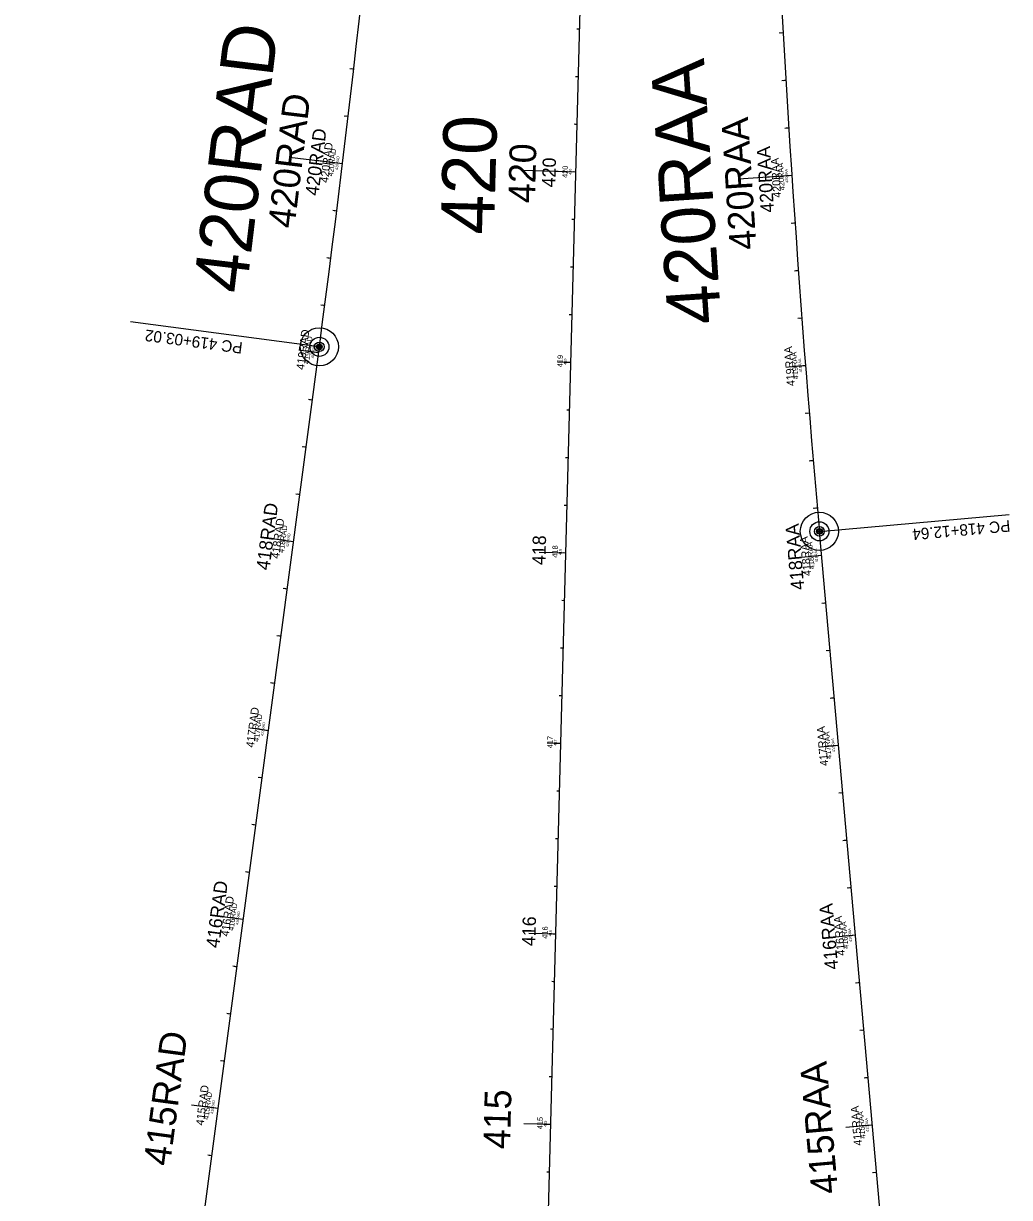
# Model space of a CAD drawing. Extents: x 564646 to 607088, y 225853 to 261760.
# Drawn here: x 598692 to 599209, y 255654 to 256270 of the extents above; entities that cross this region are included whole.
import ezdxf

# ---------------------------------------------------------------- set-up
doc = ezdxf.new("R2010")
doc.units = 0
for name, color, linetype in [('B_CONC_HIDDEN_LT', 7, 'Continuous'), ('B_CONST', 7, 'Continuous'), ('B_EXIST', 7, 'Continuous'), ('B_TEXT', 7, 'Continuous'), ('E-Easements', 7, 'Continuous'), ('E-Property Lines', 7, 'Continuous'), ('E_ALI_100', 7, 'Continuous'), ('E_RW_CorporateLimits', 7, 'Continuous'), ('E_RW_EasementUtility_Text', 7, 'Continuous'), ('E_WTR_FlowLine', 7, 'Continuous'), ('EMCS_SURVEY_PT CODES', 7, 'Continuous'), ('EMCS_SURVEY_PT ELEV', 7, 'Continuous'), ('EMCS_SURVEY_PT NOTES', 7, 'Continuous'), ('Level 33', 7, 'Continuous'), ('P-Easements Floodplain', 7, 'Continuous'), ('P-Easements Temporary', 7, 'Continuous'), ('P_ALI_100_Tic', 7, 'Continuous'), ('P_ALI_20', 7, 'Continuous'), ('P_RW_AccessPreviousProject Txt', 7, 'Continuous'), ('P_RW_EasementPerm', 7, 'Continuous'), ('P_RW_EasementTemp', 7, 'Continuous'), ('P_RW_PropertyConnector', 7, 'Continuous'), ('P_RW_Proposed', 7, 'Continuous'), ('P_WAL', 7, 'Continuous')]:
    doc.layers.add(name, color=color, linetype=linetype)

msp = doc.modelspace()

# ---------------------------------------------------------------- linework, layer by layer
at = {"layer": 'B_CONC_HIDDEN_LT'}
for p, q in [((598400.93, 234167.82), (599016.61, 257518.82)), ((598699.97, 254993.78), (598847.11, 256100.02)), ((599199.94, 254988.24), (599109.45, 256003.2))]:
    msp.add_line(p, q, dxfattribs=at)
for centre, start, end in [((590916.95, 257154.8), 352.423638, 358.489658), ((607077.84, 256713.66), 179.635421, 185.095011)]:
    msp.add_arc(centre, 8000, start, end, dxfattribs=at)
at = {"layer": 'B_CONST'}
for centre in [(598847.11, 256100.02), (599109.45, 256003.2)]:
    msp.add_circle(centre, 1.5, dxfattribs=at)
at = {"layer": 'B_EXIST'}
for centre in [(598847.11, 256100.02), (599109.45, 256003.2)]:
    msp.add_circle(centre, 5, dxfattribs=at)
at = {"layer": 'B_TEXT'}
for points in [[(598847.11, 256100.02), (598747.99, 256113.21)], [(599109.45, 256003.2), (599209.05, 256012.08)]]:
    msp.add_lwpolyline(points, dxfattribs=at)
at = {"layer": 'E-Easements'}
for centre in [(598847.11, 256100.02), (599109.45, 256003.2)]:
    msp.add_circle(centre, 2.5, dxfattribs=at)
at = {"layer": 'E_ALI_100'}
for points in [[(598982.2, 256266.91), (598983.6, 256266.88)], [(599089.04, 256264.78), (599090.44, 256264.86)], [(598863.76, 256246.04), (598865.15, 256245.88)], [(598981.54, 256241.92), (598982.94, 256241.88)], [(599090.48, 256239.82), (599091.88, 256239.9)], [(598860.88, 256221.21), (598862.27, 256221.05)], [(598980.88, 256216.93), (598982.28, 256216.89)], [(599092, 256214.86), (599093.4, 256214.94)], [(598856.54, 256196.56), (598859.32, 256196.23)], [(598978.83, 256191.98), (598981.62, 256191.9)], [(599092.2, 256189.81), (599095, 256190)], [(598854.89, 256171.58), (598856.28, 256171.41)], [(598979.57, 256166.95), (598980.97, 256166.91)], [(599095.28, 256164.96), (599096.67, 256165.05)], [(598851.78, 256146.78), (598853.17, 256146.6)], [(598978.91, 256141.96), (598980.31, 256141.92)], [(599097.03, 256140.01), (599098.43, 256140.11)], [(598848.59, 256121.99), (598849.98, 256121.81)], [(598978.25, 256116.96), (598979.65, 256116.93)], [(599098.86, 256115.08), (599100.26, 256115.18)], [(598843.94, 256097.39), (598846.71, 256097.02)], [(598976.19, 256092.01), (598978.99, 256091.94)], [(599099.38, 256090.04), (599102.17, 256090.25)], [(598842.03, 256072.43), (598843.42, 256072.24)], [(598976.93, 256066.98), (598978.33, 256066.95)], [(599102.76, 256065.22), (599104.15, 256065.33)], [(598838.73, 256047.64), (598840.12, 256047.46)], [(598976.27, 256041.99), (598977.67, 256041.95)], [(599104.82, 256040.3), (599106.22, 256040.42)], [(598835.44, 256022.86), (598836.83, 256022.68)], [(598975.61, 256017), (598977.01, 256016.96)], [(599106.97, 256015.39), (599108.36, 256015.51)], [(598830.75, 255998.27), (598833.53, 255997.9)], [(598973.55, 255992.05), (598976.35, 255991.97)], [(599107.78, 255990.36), (599110.57, 255990.61)], [(598828.85, 255973.3), (598830.23, 255973.11)], [(598974.3, 255967.02), (598975.69, 255966.98)], [(599111.4, 255965.58), (599112.79, 255965.71)], [(598825.55, 255948.52), (598826.94, 255948.33)], [(598973.64, 255942.03), (598975.04, 255941.99)], [(599113.62, 255940.68), (599115.01, 255940.81)], [(598822.25, 255923.74), (598823.64, 255923.55)], [(598972.98, 255917.03), (598974.38, 255917)], [(599115.84, 255915.78), (599117.23, 255915.9)], [(598817.57, 255899.14), (598820.34, 255898.77)], [(598970.92, 255892.08), (598973.72, 255892.01)], [(599116.66, 255890.75), (599119.45, 255891)], [(598815.66, 255874.17), (598817.05, 255873.99)], [(598971.66, 255867.05), (598973.06, 255867.01)], [(599120.28, 255865.98), (599121.67, 255866.1)], [(598812.36, 255849.39), (598813.75, 255849.21)], [(598971, 255842.06), (598972.4, 255842.02)], [(599122.5, 255841.08), (599123.89, 255841.2)], [(598809.07, 255824.61), (598810.46, 255824.42)], [(598970.34, 255817.07), (598971.74, 255817.03)], [(599124.72, 255816.18), (599126.11, 255816.3)], [(598804.38, 255800.01), (598807.16, 255799.64)], [(598968.28, 255792.11), (598971.08, 255792.04)], [(599125.54, 255791.15), (599128.33, 255791.4)], [(598802.48, 255775.04), (598803.86, 255774.86)], [(598969.02, 255767.09), (598970.42, 255767.05)], [(599129.16, 255766.37), (599130.55, 255766.5)], [(598799.18, 255750.26), (598800.57, 255750.08)], [(598968.36, 255742.1), (598969.76, 255742.06)], [(599131.38, 255741.47), (599132.77, 255741.6)], [(598795.88, 255725.48), (598797.27, 255725.3)], [(598967.71, 255717.1), (598969.11, 255717.07)], [(599133.6, 255716.57), (599134.99, 255716.69)], [(598791.2, 255700.88), (598793.98, 255700.51)], [(598965.65, 255692.15), (598968.45, 255692.08)], [(599134.43, 255691.54), (599137.21, 255691.79)], [(598789.29, 255675.92), (598790.68, 255675.73)], [(598966.39, 255667.12), (598967.79, 255667.08)], [(599138.04, 255666.77), (599139.43, 255666.89)]]:
    msp.add_lwpolyline(points, dxfattribs=at)
at = {"layer": 'E_WTR_FlowLine'}
for centre in [(598847.11, 256100.02), (599109.45, 256003.2)]:
    msp.add_circle(centre, 0.5, dxfattribs=at)
at = {"layer": 'EMCS_SURVEY_PT CODES'}
for p, q in [((598400.93, 234167.82), (599016.61, 257518.82)), ((598699.97, 254993.78), (598847.11, 256100.02)), ((599199.94, 254988.24), (599109.45, 256003.2))]:
    msp.add_line(p, q, dxfattribs=at)
for centre, start, end in [((590916.95, 257154.8), 352.423638, 358.489658), ((607077.84, 256713.66), 179.635421, 185.095011)]:
    msp.add_arc(centre, 8000, start, end, dxfattribs=at)
at = {"layer": 'EMCS_SURVEY_PT ELEV'}
for p, q in [((598400.93, 234167.82), (599016.61, 257518.82)), ((598400.93, 234167.82), (599016.61, 257518.82)), ((598699.97, 254993.78), (598847.11, 256100.02)), ((599199.94, 254988.24), (599109.45, 256003.2))]:
    msp.add_line(p, q, dxfattribs=at)
for centre, start, end in [((590916.95, 257154.8), 352.423638, 358.489658), ((607077.84, 256713.66), 179.635421, 185.095011)]:
    msp.add_arc(centre, 8000, start, end, dxfattribs=at)
at = {"layer": 'Level 33'}
for points in [[(598982.9, 256266.89), (598983.6, 256266.88)], [(599089.74, 256264.82), (599090.44, 256264.86)], [(598864.46, 256245.96), (598865.15, 256245.88)], [(598982.24, 256241.9), (598982.94, 256241.88)], [(599091.18, 256239.86), (599091.88, 256239.9)], [(598861.58, 256221.13), (598862.27, 256221.05)], [(598981.58, 256216.91), (598982.28, 256216.89)], [(599092.7, 256214.9), (599093.4, 256214.94)], [(598857.93, 256196.39), (598859.32, 256196.23)], [(598980.23, 256191.94), (598981.62, 256191.9)], [(599093.6, 256189.9), (599095, 256190)], [(598855.59, 256171.5), (598856.28, 256171.41)], [(598980.27, 256166.93), (598980.97, 256166.91)], [(599095.97, 256165), (599096.67, 256165.05)], [(598852.48, 256146.69), (598853.17, 256146.6)], [(598979.61, 256141.94), (598980.31, 256141.92)], [(599097.73, 256140.06), (599098.43, 256140.11)], [(598849.29, 256121.9), (598849.98, 256121.81)], [(598978.95, 256116.95), (598979.65, 256116.93)], [(599099.56, 256115.13), (599100.26, 256115.18)], [(598845.33, 256097.21), (598846.71, 256097.02)], [(598977.59, 256091.97), (598978.99, 256091.94)], [(599100.77, 256090.14), (599102.17, 256090.25)], [(598842.72, 256072.33), (598843.42, 256072.24)], [(598977.63, 256066.96), (598978.33, 256066.95)], [(599103.46, 256065.28), (599104.15, 256065.33)], [(598839.43, 256047.55), (598840.12, 256047.46)], [(598976.97, 256041.97), (598977.67, 256041.95)], [(599105.52, 256040.36), (599106.22, 256040.42)], [(598836.13, 256022.77), (598836.83, 256022.68)], [(598976.31, 256016.98), (598977.01, 256016.96)], [(599107.66, 256015.45), (599108.36, 256015.51)], [(598832.14, 255998.08), (598833.53, 255997.9)], [(598974.95, 255992.01), (598976.35, 255991.97)], [(599109.18, 255990.48), (599110.57, 255990.61)], [(598829.54, 255973.21), (598830.23, 255973.11)], [(598974.99, 255967), (598975.69, 255966.98)], [(599112.1, 255965.64), (599112.79, 255965.71)], [(598826.24, 255948.42), (598826.94, 255948.33)], [(598974.34, 255942.01), (598975.04, 255941.99)], [(599114.32, 255940.74), (599115.01, 255940.81)], [(598822.95, 255923.64), (598823.64, 255923.55)], [(598973.68, 255917.02), (598974.38, 255917)], [(599116.54, 255915.84), (599117.23, 255915.9)], [(598818.96, 255898.95), (598820.34, 255898.77)], [(598972.32, 255892.04), (598973.72, 255892.01)], [(599118.06, 255890.88), (599119.45, 255891)], [(598816.35, 255874.08), (598817.05, 255873.99)], [(598972.36, 255867.03), (598973.06, 255867.01)], [(599120.98, 255866.04), (599121.67, 255866.1)], [(598813.06, 255849.3), (598813.75, 255849.21)], [(598971.7, 255842.04), (598972.4, 255842.02)], [(599123.2, 255841.14), (599123.89, 255841.2)], [(598809.76, 255824.52), (598810.46, 255824.42)], [(598971.04, 255817.05), (598971.74, 255817.03)], [(599125.42, 255816.24), (599126.11, 255816.3)], [(598805.77, 255799.83), (598807.16, 255799.64)], [(598969.68, 255792.08), (598971.08, 255792.04)], [(599126.94, 255791.27), (599128.33, 255791.4)], [(598803.17, 255774.95), (598803.86, 255774.86)], [(598969.72, 255767.07), (598970.42, 255767.05)], [(599129.86, 255766.43), (599130.55, 255766.5)], [(598799.87, 255750.17), (598800.57, 255750.08)], [(598969.06, 255742.08), (598969.76, 255742.06)], [(599132.08, 255741.53), (599132.77, 255741.6)], [(598796.58, 255725.39), (598797.27, 255725.3)], [(598968.41, 255717.09), (598969.11, 255717.07)], [(599134.3, 255716.63), (599134.99, 255716.69)], [(598792.59, 255700.7), (598793.98, 255700.51)], [(598967.05, 255692.11), (598968.45, 255692.08)], [(599135.82, 255691.67), (599137.21, 255691.79)], [(598789.99, 255675.83), (598790.68, 255675.73)], [(598967.09, 255667.1), (598967.79, 255667.08)], [(599138.74, 255666.83), (599139.43, 255666.89)]]:
    msp.add_lwpolyline(points, dxfattribs=at)
at = {"layer": 'P-Easements Floodplain'}
for p, q in [((598400.93, 234167.82), (599016.61, 257518.82)), ((598699.97, 254993.78), (598847.11, 256100.02)), ((599199.94, 254988.24), (599109.45, 256003.2))]:
    msp.add_line(p, q, dxfattribs=at)
for centre, start, end in [((590916.95, 257154.8), 352.423638, 358.489658), ((607077.84, 256713.66), 179.635421, 185.095011)]:
    msp.add_arc(centre, 8000, start, end, dxfattribs=at)
at = {"layer": 'P-Easements Temporary'}
for centre in [(598847.11, 256100.02), (599109.45, 256003.2)]:
    msp.add_circle(centre, 10, dxfattribs=at)
at = {"layer": 'P_ALI_100_Tic'}
for points in [[(598831.52, 256199.58), (598859.32, 256196.23)], [(598953.63, 256192.64), (598981.62, 256191.9)], [(599067.06, 256188.16), (599095, 256190)], [(598819.65, 255999.74), (598833.53, 255997.9)], [(598962.36, 255992.34), (598976.35, 255991.97)], [(599096.63, 255989.36), (599110.57, 255990.61)], [(598793.28, 255801.49), (598807.16, 255799.64)], [(598957.09, 255792.41), (598971.08, 255792.04)], [(599114.39, 255790.15), (599128.33, 255791.4)]]:
    msp.add_lwpolyline(points, dxfattribs=at)
at = {"layer": 'P_ALI_20'}
for points in [[(598845.42, 256197.9), (598859.32, 256196.23)], [(598967.63, 256192.27), (598981.62, 256191.9)], [(599081.03, 256189.08), (599095, 256190)], [(598839.78, 256097.95), (598846.71, 256097.02)], [(598971.99, 256092.12), (598978.99, 256091.94)], [(599095.19, 256089.71), (599102.17, 256090.25)], [(598826.59, 255998.82), (598833.53, 255997.9)], [(598969.36, 255992.16), (598976.35, 255991.97)], [(599103.6, 255989.99), (599110.57, 255990.61)], [(598813.41, 255899.69), (598820.34, 255898.77)], [(598966.72, 255892.19), (598973.72, 255892.01)], [(599112.48, 255890.38), (599119.45, 255891)], [(598800.22, 255800.56), (598807.16, 255799.64)], [(598964.08, 255792.23), (598971.08, 255792.04)], [(599121.36, 255790.78), (599128.33, 255791.4)], [(598780.1, 255702.36), (598793.98, 255700.51)], [(598954.45, 255692.44), (598968.45, 255692.08)], [(599123.27, 255690.55), (599137.21, 255691.79)]]:
    msp.add_lwpolyline(points, dxfattribs=at)
at = {"layer": 'P_RW_AccessPreviousProject Txt'}
for points in [[(599088.34, 256264.74), (599090.44, 256264.86)], [(598863.07, 256246.12), (598865.15, 256245.88)], [(598863.07, 256246.12), (598865.15, 256245.88)], [(599089.78, 256239.77), (599091.88, 256239.9)], [(598860.19, 256221.29), (598862.27, 256221.05)], [(598860.19, 256221.29), (598862.27, 256221.05)], [(599091.3, 256214.81), (599093.4, 256214.94)], [(598855.15, 256196.73), (598859.32, 256196.23)], [(598855.15, 256196.73), (598859.32, 256196.23)], [(599090.81, 256189.72), (599095, 256190)], [(598854.2, 256171.67), (598856.28, 256171.41)], [(598854.2, 256171.67), (598856.28, 256171.41)], [(599094.58, 256164.91), (599096.67, 256165.05)], [(598851.09, 256146.87), (598853.17, 256146.6)], [(598851.09, 256146.87), (598853.17, 256146.6)], [(599096.33, 256139.96), (599098.43, 256140.11)], [(598847.9, 256122.08), (598849.98, 256121.81)], [(598847.9, 256122.08), (598849.98, 256121.81)], [(599098.16, 256115.02), (599100.26, 256115.18)], [(598842.55, 256097.58), (598846.71, 256097.02)], [(598842.55, 256097.58), (598846.71, 256097.02)], [(599097.98, 256089.93), (599102.17, 256090.25)], [(598841.34, 256072.52), (598843.42, 256072.24)], [(598841.34, 256072.52), (598843.42, 256072.24)], [(599102.06, 256065.16), (599104.15, 256065.33)], [(598838.04, 256047.74), (598840.12, 256047.46)], [(598838.04, 256047.74), (598840.12, 256047.46)], [(599104.13, 256040.24), (599106.22, 256040.42)], [(598834.74, 256022.95), (598836.83, 256022.68)], [(598834.74, 256022.95), (598836.83, 256022.68)], [(599106.27, 256015.33), (599108.36, 256015.51)], [(598829.37, 255998.45), (598833.53, 255997.9)], [(598829.37, 255998.45), (598833.53, 255997.9)], [(599106.39, 255990.24), (599110.57, 255990.61)], [(598828.15, 255973.39), (598830.23, 255973.11)], [(598828.15, 255973.39), (598830.23, 255973.11)], [(599110.7, 255965.52), (599112.79, 255965.71)], [(598824.86, 255948.61), (598826.94, 255948.33)], [(598824.86, 255948.61), (598826.94, 255948.33)], [(599112.92, 255940.62), (599115.01, 255940.81)], [(598821.56, 255923.83), (598823.64, 255923.55)], [(598821.56, 255923.83), (598823.64, 255923.55)], [(599115.14, 255915.72), (599117.23, 255915.9)], [(598816.18, 255899.32), (598820.34, 255898.77)], [(598816.18, 255899.32), (598820.34, 255898.77)], [(599115.27, 255890.63), (599119.45, 255891)], [(598814.97, 255874.26), (598817.05, 255873.99)], [(598814.97, 255874.26), (598817.05, 255873.99)], [(599119.58, 255865.92), (599121.67, 255866.1)], [(598811.67, 255849.48), (598813.75, 255849.21)], [(598811.67, 255849.48), (598813.75, 255849.21)], [(599121.8, 255841.01), (599123.89, 255841.2)], [(598808.37, 255824.7), (598810.46, 255824.42)], [(598808.37, 255824.7), (598810.46, 255824.42)], [(599124.02, 255816.11), (599126.11, 255816.3)], [(598803, 255800.2), (598807.16, 255799.64)], [(598803, 255800.2), (598807.16, 255799.64)], [(599124.15, 255791.03), (599128.33, 255791.4)], [(598801.78, 255775.14), (598803.86, 255774.86)], [(598801.78, 255775.14), (598803.86, 255774.86)], [(599128.46, 255766.31), (599130.55, 255766.5)], [(598798.49, 255750.36), (598800.57, 255750.08)], [(598798.49, 255750.36), (598800.57, 255750.08)], [(599130.68, 255741.41), (599132.77, 255741.6)], [(598795.19, 255725.57), (598797.27, 255725.3)], [(598795.19, 255725.57), (598797.27, 255725.3)], [(599132.9, 255716.51), (599134.99, 255716.69)], [(598789.81, 255701.07), (598793.98, 255700.51)], [(598789.81, 255701.07), (598793.98, 255700.51)], [(599133.03, 255691.42), (599137.21, 255691.79)], [(598788.6, 255676.01), (598790.68, 255675.73)], [(598788.6, 255676.01), (598790.68, 255675.73)], [(599137.34, 255666.71), (599139.43, 255666.89)]]:
    msp.add_lwpolyline(points, dxfattribs=at)
at = {"layer": 'P_RW_EasementPerm'}
for points in [[(598852.37, 256197.06), (598859.32, 256196.23)], [(598974.63, 256192.09), (598981.62, 256191.9)], [(599088.01, 256189.54), (599095, 256190)], [(598843.24, 256097.48), (598846.71, 256097.02)], [(598975.49, 256092.03), (598978.99, 256091.94)], [(599098.68, 256089.98), (599102.17, 256090.25)], [(598826.59, 255998.82), (598833.53, 255997.9)], [(598969.36, 255992.16), (598976.35, 255991.97)], [(599103.6, 255989.99), (599110.57, 255990.61)], [(598816.88, 255899.23), (598820.34, 255898.77)], [(598970.22, 255892.1), (598973.72, 255892.01)], [(599115.97, 255890.69), (599119.45, 255891)], [(598800.22, 255800.56), (598807.16, 255799.64)], [(598964.08, 255792.23), (598971.08, 255792.04)], [(599121.36, 255790.78), (599128.33, 255791.4)], [(598790.51, 255700.98), (598793.98, 255700.51)], [(598964.95, 255692.17), (598968.45, 255692.08)], [(599133.73, 255691.48), (599137.21, 255691.79)]]:
    msp.add_lwpolyline(points, dxfattribs=at)
at = {"layer": 'P_RW_EasementTemp'}
for p, q in [((598400.93, 234167.82), (599016.61, 257518.82)), ((598699.97, 254993.78), (598847.11, 256100.02)), ((599199.94, 254988.24), (599109.45, 256003.2))]:
    msp.add_line(p, q, dxfattribs=at)
for centre, start, end in [((590916.95, 257154.8), 352.423638, 358.489658), ((607077.84, 256713.66), 179.635421, 185.095011)]:
    msp.add_arc(centre, 8000, start, end, dxfattribs=at)
at = {"layer": 'P_RW_PropertyConnector'}
for p, q in [((598400.93, 234167.82), (599016.61, 257518.82)), ((598699.97, 254993.78), (598847.11, 256100.02)), ((599199.94, 254988.24), (599109.45, 256003.2))]:
    msp.add_line(p, q, dxfattribs=at)
for centre, start, end in [((590916.95, 257154.8), 352.423638, 358.489658), ((607077.84, 256713.66), 179.635421, 185.095011)]:
    msp.add_arc(centre, 8000, start, end, dxfattribs=at)
at = {"layer": 'P_WAL'}
for centre in [(598847.11, 256100.02), (599109.45, 256003.2)]:
    msp.add_circle(centre, 1, dxfattribs=at)

# ---------------------------------------------------------------- texts
for s, rotation, p in [('420RAD', 83.11818, (598854.25, 256189.34)), ('420RAA', 93.75313, (599091.3, 256182.25)), ('420', 88.48966, (598977.34, 256188.59)), ('419RAD', 82.42364, (598841.66, 256090.86)), ('419RAA', 94.46932, (599098.51, 256083.12)), ('419', 88.48966, (598974.72, 256089.31)), ('418RAD', 82.42364, (598828.48, 255991.75)), ('418', 88.48966, (598972.08, 255989.35)), ('418RAA', 95.09501, (599106.99, 255983.46)), ('417RAD', 82.42364, (598815.29, 255892.62)), ('417', 88.48966, (598969.45, 255889.38)), ('417RAA', 95.09501, (599115.87, 255883.86)), ('416RAD', 82.42364, (598802.11, 255793.5)), ('416', 88.48966, (598966.81, 255789.42)), ('416RAA', 95.09501, (599124.75, 255784.25)), ('415RAD', 82.42364, (598788.92, 255694.37)), ('415RAA', 95.09501, (599133.64, 255684.65)), ('415', 88.48966, (598964.18, 255689.45))]:
    msp.add_text(s, height=2.8, rotation=rotation).set_placement(p)
at = {"layer": 'B_TEXT'}
for s, rotation, p in [('PC 419+03.02', 172.42364, (598807.16, 256102.31)), ('PC 418+12.64', 185.09501, (599209.32, 256009.09))]:
    msp.add_text(s, height=6, rotation=rotation, dxfattribs=at).set_placement(p)
at = {"layer": 'E-Property Lines'}
for s, rotation, p in [('420RAD', 83.11818, (598808.7, 256127.39)), ('420RAA', 93.75313, (599057.99, 256112.56)), ('420', 88.48966, (598938.74, 256158.74))]:
    msp.add_text(s, height=28, rotation=rotation, dxfattribs=at).set_placement(p)
at = {"layer": 'E_RW_CorporateLimits'}
for s, rotation, p in [('420RAD', 83.11818, (598834.01, 256161.81)), ('420RAA', 93.75313, (599076.49, 256151.28)), ('420', 88.48966, (598960.18, 256175.32)), ('415RAD', 82.42364, (598768.7, 255669.79)), ('415RAA', 95.09501, (599119.32, 255656.06)), ('415', 88.48966, (598947.09, 255678.97))]:
    msp.add_text(s, height=14, rotation=rotation, dxfattribs=at).set_placement(p)
at = {"layer": 'E_RW_EasementUtility_Text'}
for s, rotation, p in [('420RAD', 83.11818, (598856.79, 256192.78)), ('420', 88.48966, (598979.48, 256190.24)), ('420RAA', 93.75313, (599093.15, 256186.12)), ('419RAD', 82.42364, (598844.19, 256093.94)), ('419', 88.48966, (598976.85, 256090.63)), ('419RAA', 94.46932, (599100.34, 256086.69)), ('418RAD', 82.42364, (598831, 255994.82)), ('418', 88.48966, (598974.22, 255990.66)), ('418RAA', 95.09501, (599108.78, 255987.03)), ('417RAD', 82.42364, (598817.82, 255895.7)), ('417', 88.48966, (598971.58, 255890.7)), ('417RAA', 95.09501, (599117.66, 255887.43)), ('416RAD', 82.42364, (598804.63, 255796.57)), ('416RAA', 95.09501, (599126.54, 255787.82)), ('416', 88.48966, (598968.95, 255790.73)), ('415RAD', 82.42364, (598791.45, 255697.44)), ('415', 88.48966, (598966.31, 255690.76)), ('415RAA', 95.09501, (599135.42, 255688.22))]:
    msp.add_text(s, height=1.4, rotation=rotation, dxfattribs=at).set_placement(p)
at = {"layer": 'EMCS_SURVEY_PT NOTES'}
for s, rotation, p in [('420RAD', 83.11818, (598851.72, 256185.9)), ('420RAD', 83.11818, (598851.72, 256185.9)), ('420RAA', 93.75313, (599089.45, 256178.38)), ('419RAD', 82.42364, (598839.13, 256087.77)), ('419RAD', 82.42364, (598839.13, 256087.77)), ('419RAA', 94.46932, (599096.68, 256079.56)), ('418RAD', 82.42364, (598825.95, 255988.68)), ('418RAD', 82.42364, (598825.95, 255988.68)), ('418RAA', 95.09501, (599105.2, 255979.89)), ('417RAD', 82.42364, (598812.76, 255889.55)), ('417RAD', 82.42364, (598812.76, 255889.55)), ('417RAA', 95.09501, (599114.08, 255880.28)), ('416RAD', 82.42364, (598799.58, 255790.43)), ('416RAD', 82.42364, (598799.58, 255790.43)), ('416RAA', 95.09501, (599122.96, 255780.68)), ('415RAD', 82.42364, (598786.39, 255691.3)), ('415RAD', 82.42364, (598786.39, 255691.3)), ('415RAA', 95.09501, (599131.85, 255681.07))]:
    msp.add_text(s, height=4.2, rotation=rotation, dxfattribs=at).set_placement(p)
at = {"layer": 'P_RW_Proposed'}
for s, rotation, p in [('420RAD', 83.11818, (598846.66, 256179.02)), ('420RAA', 93.75313, (599085.74, 256170.64)), ('420', 88.48966, (598970.9, 256183.61)), ('418RAD', 82.42364, (598820.89, 255982.53)), ('418RAA', 95.09501, (599101.62, 255972.74)), ('418', 88.48966, (598965.68, 255985.42)), ('416RAD', 82.42364, (598794.52, 255784.28)), ('416RAA', 95.09501, (599119.39, 255773.53)), ('416', 88.48966, (598960.41, 255785.49))]:
    msp.add_text(s, height=7, rotation=rotation, dxfattribs=at).set_placement(p)

doc.saveas('drawing.dxf')
